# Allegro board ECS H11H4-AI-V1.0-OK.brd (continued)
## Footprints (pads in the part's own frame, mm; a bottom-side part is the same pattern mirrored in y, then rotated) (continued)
DFN6_PT065_SM2203NSQG
  rect 0.406x0.508 smd: 1(-0.65,-0.967) 2(0,-0.967) 3(0.65,-0.967) 4(0.65,0.967) 5(0,0.967) 6(-0.65,0.967)
  rect 1.016x1.016 smd: 7(-0.27,0)
  rect 0.305x0.762 smd: 8(0.59,0.03)
DFN8_NCP5359A_1
  rect 0.305x0.635 smd: 1(-0.75,-0.925) 2(-0.25,-0.925) 3(0.25,-0.925) 4(0.75,-0.925) 5(0.75,0.925) 6(0.25,0.925) 7(-0.25,0.925) 8(-0.75,0.925)
  rect 1.2x0.8 smd: 9(0,0)
DFN10_PT05_NCP1593
  rect 0.305x0.711 smd: 1(-1,-1.46) 2(-0.5,-1.46) 3(0,-1.46) 4(0.5,-1.46) 5(1,-1.46) 6(1,1.46) 7(0.5,1.46) 8(0,1.46) 9(-0.5,1.46) 10(-1,1.46)
  rect 2.5x1.8 smd: 11(0,0)
EC2_4_H5MM
  round 1.27 hole 0.813: 1(-1,0) 2(1,0)
EC2D5_6D3_H8MM
  round 1.372 hole 1.016: 1(-1.25,0) 2(1.25,0)
EC2D5_6D3_H9MM
  round 1.372 hole 1.016: 1(-1.25,0) 2(1.25,0)
EC2D5_6D3_H11MM
  round 1.372 hole 1.016: 1(-1.25,0) 2(1.25,0)
EC3D5_8_H11MM_1P
  round 1.676 hole 1.219: 1(-1.75,0)
  round 1.372 hole 1.016: 2(1.75,0)
EC3D5_8_H13MM_1P
  round 1.676 hole 1.219: 1(-1.75,0)
  round 1.372 hole 1.016: 2(1.75,0)
ETXTALS-SPAD_1
  round 1.016 hole 0.66: 1(-6.35,-1.27) 2(-6.35,1.27)
  round 1.27 hole 0.813: 3(0,-2.54) 4(0,2.54)
FB0402_2
  oval 0.572x0.508 smd: 1(-0.476,0) 2(0.476,0)
FB0603_2
  oval 0.889x0.762 smd: 1(-0.699,0) 2(0.699,0)
FB0805_2
  oval 1.143x1.397 smd: 1(-0.953,0) 2(0.953,0)
FPC_4P10_R_1
  rect 0.2x0.675 smd: 1(-1,-0.437) 2(-0.5,-0.437) 4(0.5,-0.437) 5(1,-0.437) 6(1,0.437) 7(0.5,0.437) 9(-0.5,0.437) 10(-1,0.437)
  rect 0.4x1.55 smd: 8(0,0)
FUSE_SMD_1
  rect 1.905x3.404 smd: 1(-2.223,0) 2(2.223,0)
HDMI_19P-F_SMD-HIGH-TOP_5
  rect 0.279x2.997 smd: 1(4.5,5.077) 2(4,5.077) 3(3.5,5.077) 4(3,5.077) 5(2.5,5.077) 6(2,5.077) 7(1.5,5.077) 8(1,5.077) 9(0.5,5.077) 10(0,5.077) 11(-0.5,5.077) 12(-1,5.077) 13(-1.5,5.077) 14(-2,5.077) 15(-2.5,5.077) 16(-3,5.077) 17(-3.5,5.077) 18(-4,5.077) 19(-4.5,5.077)
  oval 1.524x3.353 hole 0.914x2.743: 20(7.25,4.142) 21(-7.25,4.142)
  oval 1.524x2.235 hole 0.914x1.626: 22(7.25,-1.818) 23(-7.25,-1.818)
HOLE8_5
  round 4.064 hole 4.064 unplated: (0,0)
  round 0.66 hole 0.356: 1(0,3.992) 2(-2.823,2.823) 3(-3.992,0) 4(-2.823,-2.823) 5(0,-3.992) 6(2.823,-2.823) 7(3.992,0) 8(2.823,2.823)
J3X1
  rect 1.372x1.372 hole 1.016: 1(-2.54,0)
  round 1.372 hole 1.016: 2(0,0) 3(2.54,0)
J4X1_WAFER
  rect 1.372x1.372 hole 1.016: 1(3.81,0)
  round 1.372 hole 1.016: 2(1.27,0) 3(-1.27,0) 4(-3.81,0)
J4X2_4P
  rect 1.372x1.372 hole 1.016: 1(-3.81,-1.27)
  round 1.372 hole 1.016: 2(-3.81,1.27) 3(-1.27,-1.27) 5(1.27,-1.27) 6(1.27,1.27) 7(3.81,-1.27) 8(3.81,1.27)
J5X2_AUDIO_1
  rect 1.372x1.372 hole 1.016: 1(-5.08,-1.27)
  round 1.372 hole 1.016: 2(-5.08,1.27) 3(-2.54,-1.27) 4(-2.54,1.27) 5(0,-1.27) 6(0,1.27) 7(2.54,-1.27) 9(5.08,-1.27) 10(5.08,1.27)
J5X2_PANEL
  rect 1.372x1.372 hole 1.016: 1(-5.08,-1.27)
  round 1.372 hole 1.016: 2(-5.08,1.27) 3(-2.54,-1.27) 4(-2.54,1.27) 5(0,-1.27) 6(0,1.27) 7(2.54,-1.27) 8(2.54,1.27) 9(5.08,-1.27)
J5X2_USB_1394
  rect 1.372x1.372 hole 1.016: 1(-5.08,-1.27)
  round 1.372 hole 1.016: 2(-5.08,1.27) 3(-2.54,-1.27) 4(-2.54,1.27) 5(0,-1.27) 6(0,1.27) 7(2.54,-1.27) 8(2.54,1.27) 10(5.08,1.27)
J7X2_PANEL_10P
  rect 1.372x1.372 hole 1.016: 1(-7.62,-1.27)
  round 1.372 hole 1.016: 2(-7.62,1.27) 3(-5.08,-1.27) 4(-5.08,1.27) 5(-2.54,-1.27) 6(-2.54,1.27) 7(0,-1.27) 8(0,1.27) 9(2.54,-1.27) 11(5.08,-1.27) 12(5.08,1.27) 13(7.62,-1.27) 14(7.62,1.27)
J10X2_TPM_4P
  rect 1.372x1.372 hole 1.016: 1(-11.43,-1.27)
  round 1.372 hole 1.016: 2(-11.43,1.27) 3(-8.89,-1.27) 5(-6.35,-1.27) 6(-6.35,1.27) 7(-3.81,-1.27) 8(-3.81,1.27) 9(-1.27,-1.27) 10(-1.27,1.27) 11(1.27,-1.27) 12(1.27,1.27) 13(3.81,-1.27) 14(3.81,1.27) 15(6.35,-1.27) 16(6.35,1.27) 17(8.89,-1.27) 18(8.89,1.27) 19(11.43,-1.27) 20(11.43,1.27)
J13X2_LPT_1
  rect 1.372x1.372 hole 1.016: 1(-15.24,-1.27)
  round 1.372 hole 1.016: 2(-12.7,-1.27) 3(-10.16,-1.27) 4(-7.62,-1.27) 5(-5.08,-1.27) 6(-2.54,-1.27) 7(0,-1.27) 8(2.54,-1.27) 9(5.08,-1.27) 10(7.62,-1.27) 11(10.16,-1.27) 12(12.7,-1.27) 13(15.24,-1.27) 14(-15.24,1.27) 15(-12.7,1.27) 16(-10.16,1.27) 17(-7.62,1.27) 18(-5.08,1.27) 19(-2.54,1.27) 20(0,1.27) 21(2.54,1.27) 22(5.08,1.27) 23(7.62,1.27) 24(10.16,1.27) 25(12.7,1.27)
JOPEN_200X60_NMNP
  rect 5.08x1.524 smd: 1(0,-0.914) 2(0,0.914)
KB_MS-MINI-DIN_1
  rect 1.676x1.676 hole 1.321: 1(-1.275,1.5)
  round 1.676 hole 1.321: 2(1.275,1.5) 3(-3.4,1.5) 4(3.4,1.5) 5(-3.4,-1) 6(3.4,-1) 7(-1.275,-5.57) 8(1.275,-5.57) 9(-3.4,-5.57) 10(3.4,-5.57) 11(-3.4,-8.07) 12(3.4,-8.07)
  round 2.692 hole 2.337: G1(0,5.3) G2(-6.75,4.5) G3(6.75,4.5) G4(-6.75,-5.57) G5(6.75,-5.57)
L0805_2
  oval 1.016x1.397 smd: 1(-0.889,0) 2(0.889,0)
LGA1151-INTEL
  round 4.064 hole 4.064 unplated: (-38.12,37.5) (-38.12,-37.5) (36.89,37.5) (36.89,-37.5)
  round 3.861 hole 3.861 unplated: (-35.21,0) (25.81,18) (25.81,-18)
  round 1.016 smd: (-19.558,-19.558) (19.812,19.812)
  round 0.66 hole 0.356: 1(-38.12,41) 2(-41.62,37.5) 3(-38.12,34) 4(-34.62,37.5) 5(36.89,41) 6(33.39,37.5) 7(36.89,34) 8(40.39,37.5) 9(-38.12,-34) 10(-41.62,-37.5) 11(-38.12,-41) 12(-34.62,-37.5) 13(36.89,-34) 14(33.39,-37.5) 15(36.89,-41) 16(40.39,-37.5)
  round 0.508 smd: A4(-16.187,18.288) A5(-15.273,18.288) AT40(18.931,-14.63) AU1(-18.931,-14.63) AU39(18.016,-15.545) AU40(18.931,-15.545) AV1(-18.931,-15.545) AV2(-18.016,-15.545) AV38(17.102,-16.459) AV39(18.016,-16.459) AW2(-18.016,-16.459) AW3(-17.102,-16.459) AW37(16.187,-17.374) AW38(17.102,-17.374) AY3(-17.102,-17.374) AY4(-16.187,-17.374) B3(-17.102,17.374) B4(-16.187,17.374) B37(16.187,16.459) B38(17.102,16.459) B39(18.016,16.459) C2(-18.016,16.459) C3(-17.102,16.459) C39(18.016,15.545) C40(18.931,15.545) D1(-18.931,15.545) D2(-18.016,15.545) D40(18.931,14.63) E40(18.931,13.716)
  round 0.429 smd: A6(-14.359,18.288) A7(-13.444,18.288) A25(3.015,18.288) A26(3.929,18.288) A27(4.844,18.288) A28(5.758,18.288) A29(6.673,18.288) A30(7.587,18.288) AA5(-15.273,0) AA6(-14.359,0) AA7(-13.444,0) AA8(-12.53,0) AA33(12.53,-0.914) AA34(13.444,-0.914) AA35(14.359,-0.914) AA36(15.273,-0.914) AA37(16.187,-0.914) AA38(17.102,-0.914) AB5(-15.273,-0.914) AB6(-14.359,-0.914) AB7(-13.444,-0.914) AB8(-12.53,-0.914) AB33(12.53,-1.829) AB34(13.444,-1.829) AB35(14.359,-1.829) AB36(15.273,-1.829) AB37(16.187,-1.829) AC5(-15.273,-1.829) AC6(-14.359,-1.829) AC7(-13.444,-1.829) AC8(-12.53,-1.829) AC33(12.53,-2.743) AC34(13.444,-2.743) AC35(14.359,-2.743) AC36(15.273,-2.743) AC37(16.187,-2.743) AD3(-17.102,-2.743) AD4(-16.187,-2.743) AD5(-15.273,-2.743) AD6(-14.359,-2.743) AD7(-13.444,-2.743) AD8(-12.53,-2.743) AD33(12.53,-3.658) AD34(13.444,-3.658) AD35(14.359,-3.658) AD36(15.273,-3.658) AD37(16.187,-3.658) AE3(-17.102,-3.658) AE4(-16.187,-3.658) AE5(-15.273,-3.658) AE6(-14.359,-3.658) AE7(-13.444,-3.658) AE8(-12.53,-3.658) AE33(12.53,-4.572) AE34(13.444,-4.572) AE35(14.359,-4.572) AE36(15.273,-4.572) AE37(16.187,-4.572) AE38(17.102,-4.572) AF4(-16.187,-4.572) AF5(-15.273,-4.572) AF6(-14.359,-4.572) AF7(-13.444,-4.572) AF8(-12.53,-4.572) AF33(12.53,-5.486) AF34(13.444,-5.486) AF35(14.359,-5.486) AF36(15.273,-5.486) AF37(16.187,-5.486) AF38(17.102,-5.486) AG4(-16.187,-5.486) AG5(-15.273,-5.486) AG6(-14.359,-5.486) AG7(-13.444,-5.486) AG8(-12.53,-5.486) AG33(12.53,-6.401) AG34(13.444,-6.401) AG35(14.359,-6.401) AG36(15.273,-6.401) AG37(16.187,-6.401) AG38(17.102,-6.401) AH3(-17.102,-6.401) AH4(-16.187,-6.401) AH5(-15.273,-6.401) AH6(-14.359,-6.401) AH7(-13.444,-6.401) AH8(-12.53,-6.401) AH33(12.53,-7.315) AH34(13.444,-7.315) AH35(14.359,-7.315) AH36(15.273,-7.315) AH37(16.187,-7.315) AH38(17.102,-7.315) AJ3(-17.102,-7.315) AJ4(-16.187,-7.315) AJ5(-15.273,-7.315) AJ6(-14.359,-7.315) AJ7(-13.444,-7.315) AJ8(-12.53,-7.315) AJ9(-11.615,-7.315) AJ11(-7.587,-8.23) AJ12(-6.673,-8.23) AJ13(-5.758,-8.23) AJ14(-4.844,-8.23) AJ15(-3.929,-8.23) AJ16(-3.015,-8.23) AJ17(-2.101,-8.23) AJ18(-1.186,-8.23) AJ19(-0.272,-8.23) AJ20(0.643,-8.23) AJ21(1.557,-8.23) AJ22(2.471,-8.23) AJ23(3.386,-8.23) AJ24(4.3,-8.23) AJ25(5.215,-8.23) AJ26(6.129,-8.23) AJ27(7.043,-8.23) AJ28(7.958,-8.23) AJ29(8.872,-8.23) AJ30(9.787,-8.23) AJ31(10.701,-8.23) AJ32(11.615,-8.23) AJ33(12.53,-8.23) AJ34(13.444,-8.23) AJ35(14.359,-8.23) AJ36(15.273,-8.23) AJ37(16.187,-8.23) AJ38(17.102,-8.23) AK3(-17.102,-8.23) AK4(-16.187,-8.23) AK5(-15.273,-8.23) AK6(-14.359,-8.23) AK7(-13.444,-8.23) AK8(-12.53,-8.23) AK9(-11.615,-8.23) AK10(-10.701,-8.23) AK11(-7.587,-9.144) AK12(-6.673,-9.144) AK13(-5.758,-9.144) AK14(-4.844,-9.144) AK15(-3.929,-9.144) AK16(-3.015,-9.144) AK17(-2.101,-9.144) AK18(-1.186,-9.144) AK19(-0.272,-9.144) AK20(0.643,-9.144) AK21(1.557,-9.144) AK22(2.471,-9.144) AK23(3.386,-9.144) AK24(4.3,-9.144) AK25(5.215,-9.144) AK26(6.129,-9.144) AK27(7.043,-9.144) AK28(7.958,-9.144) AK29(8.872,-9.144) AK30(9.787,-9.144) AK31(10.701,-9.144) AK32(11.615,-9.144) AK33(12.53,-9.144) AK34(13.444,-9.144) AK35(14.359,-9.144) AK36(15.273,-9.144) AK37(16.187,-9.144) AK38(17.102,-9.144) AL3(-17.102,-9.144) AL4(-16.187,-9.144) AL5(-15.273,-9.144) AL6(-14.359,-9.144) AL7(-13.444,-9.144) AL8(-12.53,-9.144) AL9(-11.615,-9.144) AL10(-10.701,-9.144) AL11(-7.587,-10.058) AL12(-6.673,-10.058) AL13(-5.758,-10.058) AL14(-4.844,-10.058) AL15(-3.929,-10.058) AL16(-3.015,-10.058) AL17(-2.101,-10.058) AL18(-1.186,-10.058) AL19(-0.272,-10.058) AL20(0.643,-10.058) AL21(1.557,-10.058) AL22(2.471,-10.058) AL23(3.386,-10.058) AL24(4.3,-10.058) AL25(5.215,-10.058) AL26(6.129,-10.058) AL27(7.043,-10.058) AL28(7.958,-10.058) AL29(8.872,-10.058) AL30(9.787,-10.058) AL31(10.701,-10.058) AL32(11.615,-10.058) AL33(12.53,-10.058) AL34(13.444,-10.058) AL35(14.359,-10.058) AL36(15.273,-10.058) AL37(16.187,-10.058) AL38(17.102,-10.058) AM3(-17.102,-10.058) AM4(-16.187,-10.058) AM5(-15.273,-10.058) AM6(-14.359,-10.058) AM7(-13.444,-10.058) AM8(-12.53,-10.058) AM9(-11.615,-10.058) AM10(-10.701,-10.058) AM11(-7.587,-10.973) AM12(-6.673,-10.973) AM13(-5.758,-10.973) AM14(-4.844,-10.973) AM15(-3.929,-10.973) AM16(-3.015,-10.973) AM17(-2.101,-10.973) AM18(-1.186,-10.973) AM19(-0.272,-10.973) AM20(0.643,-10.973) AM21(1.557,-10.973) AM22(2.471,-10.973) AM23(3.386,-10.973) AM24(4.3,-10.973) AM25(5.215,-10.973) AM26(6.129,-10.973) AM27(7.043,-10.973) AM28(7.958,-10.973) AM29(8.872,-10.973) AM30(9.787,-10.973) AM31(10.701,-10.973) AM32(11.615,-10.973) AM33(12.53,-10.973) AM34(13.444,-10.973) AM35(14.359,-10.973) AM36(15.273,-10.973) AM37(16.187,-10.973) AM38(17.102,-10.973) AN3(-17.102,-10.973) AN4(-16.187,-10.973) AN5(-15.273,-10.973) AN6(-14.359,-10.973) AN7(-13.444,-10.973) AN8(-12.53,-10.973) AN9(-11.615,-10.973) AN10(-10.701,-10.973) AN11(-7.587,-11.887) AN12(-6.673,-11.887) AN13(-5.758,-11.887) AN14(-4.844,-11.887) AN15(-3.929,-11.887) AN16(-3.015,-11.887) AN17(-2.101,-11.887) AN18(-1.186,-11.887) AN19(-0.272,-11.887) AN20(0.643,-11.887) AN21(1.557,-11.887) AN22(2.471,-11.887) AN23(3.386,-11.887) AN24(4.3,-11.887) AN25(5.215,-11.887) AN26(6.129,-11.887) AN27(7.043,-11.887) AN28(7.958,-11.887) AN29(8.872,-11.887) AN30(9.787,-11.887) AN31(10.701,-11.887) AN32(11.615,-11.887) AN33(12.53,-11.887) AN34(13.444,-11.887) AN35(14.359,-11.887) AN36(15.273,-11.887) AN37(16.187,-11.887) AN38(17.102,-11.887) AP3(-17.102,-11.887) AP4(-16.187,-11.887) AP5(-15.273,-11.887) AP6(-14.359,-11.887) AP7(-13.444,-11.887) AP8(-12.53,-11.887) AP9(-11.615,-11.887) AP10(-10.701,-11.887) AP11(-7.587,-12.802) AP12(-6.673,-12.802) AP13(-5.758,-12.802) AP14(-4.844,-12.802) AP15(-3.929,-12.802) AP16(-3.015,-12.802) AP17(-2.101,-12.802) AP18(-1.186,-12.802) AP19(-0.272,-12.802) AP20(0.643,-12.802) AP21(1.557,-12.802) AP22(2.471,-12.802) AP23(3.386,-12.802) AP24(4.3,-12.802) AP25(5.215,-12.802) AP26(6.129,-12.802) AP27(7.043,-12.802) AP28(7.958,-12.802) AP29(8.872,-12.802) AP30(9.787,-12.802) AP31(10.701,-12.802) AP32(11.615,-12.802) AP33(12.53,-12.802) AP34(13.444,-12.802) AP35(14.359,-12.802) AP36(15.273,-12.802) AP37(16.187,-12.802) AP38(17.102,-12.802) AR3(-17.102,-12.802) AR4(-16.187,-12.802) AR5(-15.273,-12.802) AR6(-14.359,-12.802) AR7(-13.444,-12.802) AR8(-12.53,-12.802) AR9(-11.615,-12.802) AR10(-10.701,-12.802) AR11(-7.587,-13.716) AR12(-6.673,-13.716) AR13(-5.758,-13.716) AR14(-4.844,-13.716) AR15(-3.929,-13.716) AR16(-3.015,-13.716) AR17(-2.101,-13.716) AR18(-1.186,-13.716) AR19(-0.272,-13.716) AR20(0.643,-13.716) AR21(1.557,-13.716) AR22(2.471,-13.716) AR23(3.386,-13.716) AR24(4.3,-13.716) AR25(5.215,-13.716) AR26(6.129,-13.716) AR27(7.043,-13.716) AR28(7.958,-13.716) AR29(8.872,-13.716) AR30(9.787,-13.716) AR31(10.701,-13.716) AR32(11.615,-13.716) AR33(12.53,-13.716) AR34(13.444,-13.716) AR35(14.359,-13.716) AR36(15.273,-13.716) AR37(16.187,-13.716) AR38(17.102,-13.716) AT3(-17.102,-13.716) AT4(-16.187,-13.716) AT5(-15.273,-13.716) AT6(-14.359,-13.716) AT7(-13.444,-13.716) AT8(-12.53,-13.716) AT9(-11.615,-13.716) AT10(-10.701,-13.716) AT11(-7.587,-14.63) AT12(-6.673,-14.63) AT13(-5.758,-14.63) AT14(-4.844,-14.63) AT15(-3.929,-14.63) AT16(-3.015,-14.63) AT17(-2.101,-14.63) AT18(-1.186,-14.63) AT19(-0.272,-14.63) AT20(0.643,-14.63) AT21(1.557,-14.63) AT22(2.471,-14.63) AT23(3.386,-14.63) AT24(4.3,-14.63) AT25(5.215,-14.63) AT26(6.129,-14.63) AT27(7.043,-14.63) AT28(7.958,-14.63) AT29(8.872,-14.63) AT30(9.787,-14.63) AT31(10.701,-14.63) AT32(11.615,-14.63) AT33(12.53,-14.63) AT34(13.444,-14.63) AT35(14.359,-14.63) AT36(15.273,-14.63) AT37(16.187,-14.63) AT38(17.102,-14.63) AU3(-17.102,-14.63) AU4(-16.187,-14.63) AU5(-15.273,-14.63) AU6(-14.359,-14.63) AU7(-13.444,-14.63) AU8(-12.53,-14.63) AU9(-11.615,-14.63) AU10(-10.701,-14.63) AU11(-7.587,-15.545) AU12(-6.673,-15.545) AU13(-5.758,-15.545) AU14(-4.844,-15.545) AU15(-3.929,-15.545) AU16(-3.015,-15.545) AU17(-2.101,-15.545) AU18(-1.186,-15.545) AU19(-0.272,-15.545) AU20(0.643,-15.545) AU21(1.557,-15.545) AU24(4.3,-15.545) AU25(5.215,-15.545) AU26(6.129,-15.545) AU27(7.043,-15.545) AU28(7.958,-15.545) AU29(8.872,-15.545) AU30(9.787,-15.545) AU31(10.701,-15.545) AU32(11.615,-15.545) AU33(12.53,-15.545) AU34(13.444,-15.545) AU35(14.359,-15.545) AU36(15.273,-15.545) AU37(16.187,-15.545) AU38(17.102,-15.545) AV3(-17.102,-15.545) AV4(-16.187,-15.545) AV5(-15.273,-15.545) AV6(-14.359,-15.545) AV7(-13.444,-15.545) AV8(-12.53,-15.545) AV9(-11.615,-15.545) AV10(-10.701,-15.545) AV11(-7.587,-16.459) AV12(-6.673,-16.459) AV13(-5.758,-16.459) AV14(-4.844,-16.459) AV24(4.3,-16.459) AV25(5.215,-16.459) AV28(7.958,-16.459) AV29(8.872,-16.459) AV37(16.187,-16.459) AW4(-16.187,-16.459) AW9(-11.615,-16.459) AW10(-10.701,-16.459) AW11(-7.587,-17.374) AW12(-6.673,-17.374) AW13(-5.758,-17.374) AW14(-4.844,-17.374) AY10(-10.701,-17.374) B5(-15.273,17.374) B6(-14.359,17.374) B7(-13.444,17.374) B25(3.015,17.374) B26(3.929,17.374) B27(4.844,17.374) B28(5.758,17.374) B29(6.673,17.374) B30(7.587,17.374) B31(10.701,16.459) B32(11.615,16.459) B33(12.53,16.459) B34(13.444,16.459) B35(14.359,16.459) B36(15.273,16.459) C4(-16.187,16.459) C5(-15.273,16.459) C6(-14.359,16.459) C7(-13.444,16.459) C8(-12.53,16.459) C9(-11.615,16.459) C12(-8.872,16.459) C13(-7.958,16.459) C14(-7.043,16.459) C15(-6.129,16.459) C16(-5.215,16.459) C17(-4.3,16.459) C25(3.015,16.459) C26(3.929,16.459) C27(4.844,16.459) C28(5.758,16.459) C29(6.673,16.459) C30(7.587,16.459) C31(10.701,15.545) C32(11.615,15.545) C33(12.53,15.545) C34(13.444,15.545) C35(14.359,15.545) C36(15.273,15.545) C37(16.187,15.545) C38(17.102,15.545) D3(-17.102,15.545) D4(-16.187,15.545) D5(-15.273,15.545) D6(-14.359,15.545) D7(-13.444,15.545) D8(-12.53,15.545) D9(-11.615,15.545) D10(-10.701,15.545) D11(-9.787,15.545) D12(-8.872,15.545) D13(-7.958,15.545) D14(-7.043,15.545) D15(-6.129,15.545) D16(-5.215,15.545) D17(-4.3,15.545) D24(2.101,15.545) D25(3.015,15.545) D26(3.929,15.545) D27(4.844,15.545) D28(5.758,15.545) D29(6.673,15.545) D30(7.587,15.545) D31(10.701,14.63) D32(11.615,14.63) D33(12.53,14.63) D34(13.444,14.63) D35(14.359,14.63) D36(15.273,14.63) D37(16.187,14.63) D38(17.102,14.63) D39(18.016,14.63) E3(-17.102,14.63) E4(-16.187,14.63) E5(-15.273,14.63) E6(-14.359,14.63) E7(-13.444,14.63) E8(-12.53,14.63) E9(-11.615,14.63) E10(-10.701,14.63) E11(-9.787,14.63) E12(-8.872,14.63) E13(-7.958,14.63) E14(-7.043,14.63) E15(-6.129,14.63) E16(-5.215,14.63) E17(-4.3,14.63) E18(-3.386,14.63) E19(-2.471,14.63) E21(-0.643,14.63) E23(1.186,14.63) E24(2.101,14.63) E25(3.015,14.63) E26(3.929,14.63) E27(4.844,14.63) E28(5.758,14.63) E29(6.673,14.63) E30(7.587,14.63) E31(10.701,13.716) E32(11.615,13.716) E33(12.53,13.716) E34(13.444,13.716) E35(14.359,13.716) E36(15.273,13.716) E37(16.187,13.716) E38(17.102,13.716) E39(18.016,13.716) F4(-16.187,13.716) F5(-15.273,13.716) F6(-14.359,13.716) F7(-13.444,13.716) F8(-12.53,13.716) F9(-11.615,13.716) F10(-10.701,13.716) F11(-9.787,13.716) F12(-8.872,13.716) F13(-7.958,13.716) F14(-7.043,13.716) F15(-6.129,13.716) F16(-5.215,13.716) F17(-4.3,13.716) F18(-3.386,13.716) F19(-2.471,13.716) F20(-1.557,13.716) F21(-0.643,13.716) F22(0.272,13.716) F23(1.186,13.716) F24(2.101,13.716) F25(3.015,13.716) F26(3.929,13.716) F27(4.844,13.716) F28(5.758,13.716) F29(6.673,13.716) F30(7.587,13.716) F31(10.701,12.802) F32(11.615,12.802) F33(12.53,12.802) F34(13.444,12.802) F35(14.359,12.802) F36(15.273,12.802) F37(16.187,12.802) F38(17.102,12.802) F39(18.016,12.802) F40(18.931,12.802) G3(-17.102,12.802) G4(-16.187,12.802) G5(-15.273,12.802) G6(-14.359,12.802) G7(-13.444,12.802) G8(-12.53,12.802) G9(-11.615,12.802) G10(-10.701,12.802) G11(-9.787,12.802) G12(-8.872,12.802) G13(-7.958,12.802) G14(-7.043,12.802) G15(-6.129,12.802) G16(-5.215,12.802) G17(-4.3,12.802) G18(-3.386,12.802) G19(-2.471,12.802) G20(-1.557,12.802) G21(-0.643,12.802) G22(0.272,12.802) G23(1.186,12.802) G24(2.101,12.802) G25(3.015,12.802) G26(3.929,12.802) G27(4.844,12.802) G28(5.758,12.802) G29(6.673,12.802) G30(7.587,12.802) G31(10.701,11.887) G32(11.615,11.887) G33(12.53,11.887) G34(13.444,11.887) G35(14.359,11.887) G36(15.273,11.887) G37(16.187,11.887) G38(17.102,11.887) G39(18.016,11.887) G40(18.931,11.887) H4(-16.187,11.887) H5(-15.273,11.887) H6(-14.359,11.887) H7(-13.444,11.887) H8(-12.53,11.887) H9(-11.615,11.887) H10(-10.701,11.887) H11(-9.787,11.887) H12(-8.872,11.887) H13(-7.958,11.887) H14(-7.043,11.887) H15(-6.129,11.887) H16(-5.215,11.887) H17(-4.3,11.887) H18(-3.386,11.887) H19(-2.471,11.887) H20(-1.557,11.887) H21(-0.643,11.887) H22(0.272,11.887) H23(1.186,11.887) H24(2.101,11.887) H25(3.015,11.887) H26(3.929,11.887) H27(4.844,11.887) H28(5.758,11.887) H29(6.673,11.887) H30(7.587,11.887) H31(10.701,10.973) H32(11.615,10.973) H33(12.53,10.973) H34(13.444,10.973) H35(14.359,10.973) H36(15.273,10.973) H37(16.187,10.973) H38(17.102,10.973) H39(18.016,10.973) H40(18.931,10.973) J3(-17.102,10.973) J4(-16.187,10.973) J5(-15.273,10.973) J6(-14.359,10.973) J7(-13.444,10.973) J8(-12.53,10.973) J9(-11.615,10.973) J10(-10.701,10.973) J11(-9.787,10.973) J12(-8.872,10.973) J13(-7.958,10.973) J14(-7.043,10.973) J15(-6.129,10.973) J16(-5.215,10.973) J17(-4.3,10.973) J18(-3.386,10.973) J19(-2.471,10.973) J20(-1.557,10.973) J21(-0.643,10.973) J22(0.272,10.973) J23(1.186,10.973) J24(2.101,10.973) J25(3.015,10.973) J26(3.929,10.973) J27(4.844,10.973) J28(5.758,10.973) J29(6.673,10.973) J30(7.587,10.973) J31(10.701,10.058) J32(11.615,10.058) J33(12.53,10.058) J34(13.444,10.058) J35(14.359,10.058) J36(15.273,10.058) J37(16.187,10.058) J38(17.102,10.058) J39(18.016,10.058) J40(18.931,10.058) K4(-16.187,10.058) K5(-15.273,10.058) K6(-14.359,10.058) K7(-13.444,10.058) K8(-12.53,10.058) K9(-11.615,10.058) K10(-10.701,10.058) K11(-9.787,10.058) K12(-8.872,10.058) K13(-7.958,10.058) K14(-7.043,10.058) K15(-6.129,10.058) K16(-5.215,10.058) K17(-4.3,10.058) K18(-3.386,10.058) K19(-2.471,10.058) K20(-1.557,10.058) K21(-0.643,10.058) K22(0.272,10.058) K23(1.186,10.058) K24(2.101,10.058) K25(3.015,10.058) K26(3.929,10.058) K27(4.844,10.058) K28(5.758,10.058) K29(6.673,10.058) K30(7.587,10.058) K31(10.701,9.144) K32(11.615,9.144) K33(12.53,9.144) K34(13.444,9.144) K35(14.359,9.144) K36(15.273,9.144) K37(16.187,9.144) K38(17.102,9.144) K39(18.016,9.144) K40(18.931,9.144) L3(-17.102,9.144) L4(-16.187,9.144) L5(-15.273,9.144) L6(-14.359,9.144) L7(-13.444,9.144) L8(-12.53,9.144) L9(-11.615,9.144) L10(-10.701,9.144) L11(-9.787,9.144) L12(-8.872,9.144) L13(-7.958,9.144) L14(-7.043,9.144) L15(-6.129,9.144) L16(-5.215,9.144) L17(-4.3,9.144) L18(-3.386,9.144) L19(-2.471,9.144) L20(-1.557,9.144) L21(-0.643,9.144) L22(0.272,9.144) L23(1.186,9.144) L24(2.101,9.144) L25(3.015,9.144) L26(3.929,9.144) L27(4.844,9.144) L28(5.758,9.144) L29(6.673,9.144) L30(7.587,9.144) L31(10.701,8.23) L32(11.615,8.23) L33(12.53,8.23) L34(13.444,8.23) L35(14.359,8.23) L36(15.273,8.23) L37(16.187,8.23) L38(17.102,8.23) L39(18.016,8.23) L40(18.931,8.23) M4(-16.187,8.23) M5(-15.273,8.23) M6(-14.359,8.23) M7(-13.444,8.23) M8(-12.53,8.23) M9(-11.615,8.23) M10(-10.701,8.23) M11(-9.787,8.23) M12(-8.872,8.23) M13(-7.958,8.23) M14(-7.043,8.23) M15(-6.129,8.23) M16(-5.215,8.23) M17(-4.3,8.23) M18(-3.386,8.23) M19(-2.471,8.23) M20(-1.557,8.23) M21(-0.643,8.23) M22(0.272,8.23) M23(1.186,8.23) M24(2.101,8.23) M25(3.015,8.23) M26(3.929,8.23) M27(4.844,8.23) M28(5.758,8.23) M29(6.673,8.23) M30(7.587,8.23) M32(11.615,7.315) M33(12.53,7.315) M34(13.444,7.315) M35(14.359,7.315) M36(15.273,7.315) M37(16.187,7.315) M38(17.102,7.315) M39(18.016,7.315) M40(18.931,7.315) N3(-17.102,7.315) N4(-16.187,7.315) N5(-15.273,7.315) N6(-14.359,7.315) N7(-13.444,7.315) N8(-12.53,7.315) N33(12.53,6.401) N34(13.444,6.401) N35(14.359,6.401) N36(15.273,6.401) N37(16.187,6.401) N38(17.102,6.401) N39(18.016,6.401) N40(18.931,6.401) P4(-16.187,6.401) P5(-15.273,6.401) P6(-14.359,6.401) P7(-13.444,6.401) P8(-12.53,6.401) P33(12.53,5.486) P34(13.444,5.486) P35(14.359,5.486) P36(15.273,5.486) P37(16.187,5.486) P38(17.102,5.486) P39(18.016,5.486) P40(18.931,5.486) R3(-17.102,5.486) R4(-16.187,5.486) R5(-15.273,5.486) R6(-14.359,5.486) R7(-13.444,5.486) R8(-12.53,5.486) R33(12.53,4.572) R34(13.444,4.572) R35(14.359,4.572) R36(15.273,4.572) R37(16.187,4.572) R38(17.102,4.572) R39(18.016,4.572) R40(18.931,4.572) T4(-16.187,4.572) T5(-15.273,4.572) T6(-14.359,4.572) T7(-13.444,4.572) T8(-12.53,4.572) T33(12.53,3.658) T34(13.444,3.658) T35(14.359,3.658) T36(15.273,3.658) T37(16.187,3.658) T38(17.102,3.658) T39(18.016,3.658) T40(18.931,3.658) U4(-16.187,3.658) U5(-15.273,3.658) U6(-14.359,3.658) U7(-13.444,3.658) U8(-12.53,3.658) U33(12.53,2.743) U34(13.444,2.743) U35(14.359,2.743) U36(15.273,2.743) U37(16.187,2.743) U38(17.102,2.743) U39(18.016,2.743) U40(18.931,2.743) V4(-16.187,2.743) V5(-15.273,2.743) V6(-14.359,2.743) V7(-13.444,2.743) V8(-12.53,2.743) V33(12.53,1.829) V34(13.444,1.829) V35(14.359,1.829) V36(15.273,1.829) V37(16.187,1.829) V38(17.102,1.829) V39(18.016,1.829) V40(18.931,1.829) W4(-16.187,1.829) W5(-15.273,1.829) W6(-14.359,1.829) W7(-13.444,1.829) W8(-12.53,1.829) W33(12.53,0.914) W34(13.444,0.914) W35(14.359,0.914) W36(15.273,0.914) W37(16.187,0.914) W38(17.102,0.914) Y5(-15.273,0.914) Y6(-14.359,0.914) Y7(-13.444,0.914) Y8(-12.53,0.914) Y33(12.53,0) Y34(13.444,0) Y35(14.359,0) Y36(15.273,0) Y37(16.187,0) Y38(17.102,0)
  oval 0.356x0.457 smd: A11(-9.787,18.288) A12(-8.872,18.288) A13(-7.958,18.288) A14(-7.043,18.288) A15(-6.129,18.288) A16(-5.215,18.288) A17(-4.3,18.288) A18(-3.386,18.288) A23(1.186,18.288) A24(2.101,18.288) AU22(2.471,-15.545) AU23(3.386,-15.545) AV15(-3.929,-16.459) AV16(-3.015,-16.459) AV17(-2.101,-16.459) AV18(-1.186,-16.459) AV19(-0.272,-16.459) AV20(0.643,-16.459) AV21(1.557,-16.459) AV22(2.471,-16.459) AV23(3.386,-16.459) AV26(6.129,-16.459) AV27(7.043,-16.459) AV30(9.787,-16.459) AV31(10.701,-16.459) AV32(11.615,-16.459) AV33(12.53,-16.459) AV34(13.444,-16.459) AV35(14.359,-16.459) AV36(15.273,-16.459) AW5(-15.273,-16.459) AW6(-14.359,-16.459) AW7(-13.444,-16.459) AW8(-12.53,-16.459) AW15(-3.929,-17.374) AW16(-3.015,-17.374) AW17(-2.101,-17.374) AW18(-1.186,-17.374) AW23(3.386,-17.374) AW24(4.3,-17.374) AW25(5.215,-17.374) AW26(6.129,-17.374) AW27(7.043,-17.374) AW28(7.958,-17.374) AW29(8.872,-17.374) AW30(9.787,-17.374) AW31(10.701,-17.374) AW32(11.615,-17.374) AW33(12.53,-17.374) AW34(13.444,-17.374) AW35(14.359,-17.374) AW36(15.273,-17.374) AY5(-15.273,-17.374) AY6(-14.359,-17.374) AY7(-13.444,-17.374) AY8(-12.53,-17.374) AY9(-11.615,-17.374) AY11(-7.587,-18.288) AY12(-6.673,-18.288) AY13(-5.758,-18.288) AY14(-4.844,-18.288) AY15(-3.929,-18.288) AY16(-3.015,-18.288) AY17(-2.101,-18.288) AY18(-1.186,-18.288) AY23(3.386,-18.288) AY24(4.3,-18.288) AY25(5.215,-18.288) AY26(6.129,-18.288) AY27(7.043,-18.288) AY28(7.958,-18.288) AY29(8.872,-18.288) AY30(9.787,-18.288) AY31(10.701,-18.288) B8(-12.53,17.374) B9(-11.615,17.374) B10(-10.701,17.374) B11(-9.787,17.374) B12(-8.872,17.374) B13(-7.958,17.374) B14(-7.043,17.374) B15(-6.129,17.374) B16(-5.215,17.374) B17(-4.3,17.374) B18(-3.386,17.374) B23(1.186,17.374) B24(2.101,17.374) C10(-10.701,16.459) C11(-9.787,16.459) C18(-3.386,16.459) C19(-2.471,16.459) C20(-1.557,16.459) C21(-0.643,16.459) C22(0.272,16.459) C23(1.186,16.459) C24(2.101,16.459) D18(-3.386,15.545) D19(-2.471,15.545) D20(-1.557,15.545) D21(-0.643,15.545) D22(0.272,15.545) D23(1.186,15.545) E20(-1.557,14.63) E22(0.272,14.63)
  oval 0.457x0.356 smd: AA3(-17.102,0) AA4(-16.187,0) AB3(-17.102,-0.914) AB4(-16.187,-0.914) AB38(17.102,-1.829) AB39(18.016,-1.829) AB40(18.931,-1.829) AC1(-18.931,-1.829) AC2(-18.016,-1.829) AC3(-17.102,-1.829) AC4(-16.187,-1.829) AC38(17.102,-2.743) AC39(18.016,-2.743) AC40(18.931,-2.743) AD1(-18.931,-2.743) AD2(-18.016,-2.743) AD38(17.102,-3.658) AD39(18.016,-3.658) AD40(18.931,-3.658) AE1(-18.931,-3.658) AE2(-18.016,-3.658) AE39(18.016,-4.572) AE40(18.931,-4.572) AF1(-18.931,-4.572) AF2(-18.016,-4.572) AF3(-17.102,-4.572) AF39(18.016,-5.486) AF40(18.931,-5.486) AG1(-18.931,-5.486) AG2(-18.016,-5.486) AG3(-17.102,-5.486) AG39(18.016,-6.401) AG40(18.931,-6.401) AH1(-18.931,-6.401) AH2(-18.016,-6.401) AH39(18.016,-7.315) AH40(18.931,-7.315) AJ1(-18.931,-7.315) AJ2(-18.016,-7.315) AJ39(18.016,-8.23) AJ40(18.931,-8.23) AK1(-18.931,-8.23) AK2(-18.016,-8.23) AK39(18.016,-9.144) AK40(18.931,-9.144) AL1(-18.931,-9.144) AL2(-18.016,-9.144) AL39(18.016,-10.058) AL40(18.931,-10.058) AM1(-18.931,-10.058) AM2(-18.016,-10.058) AM39(18.016,-10.973) AM40(18.931,-10.973) AN1(-18.931,-10.973) AN2(-18.016,-10.973) AN39(18.016,-11.887) AN40(18.931,-11.887) AP1(-18.931,-11.887) AP2(-18.016,-11.887) AP39(18.016,-12.802) AP40(18.931,-12.802) AR1(-18.931,-12.802) AR2(-18.016,-12.802) AR39(18.016,-13.716) AR40(18.931,-13.716) AT1(-18.931,-13.716) AT2(-18.016,-13.716) AT39(18.016,-14.63) AU2(-18.016,-14.63) E1(-18.931,14.63) E2(-18.016,14.63) F1(-18.931,13.716) F2(-18.016,13.716) F3(-17.102,13.716) G1(-18.931,12.802) G2(-18.016,12.802) H1(-18.931,11.887) H2(-18.016,11.887) H3(-17.102,11.887) J1(-18.931,10.973) J2(-18.016,10.973) K1(-18.931,10.058) K2(-18.016,10.058) K3(-17.102,10.058) L1(-18.931,9.144) L2(-18.016,9.144) M1(-18.931,8.23) M2(-18.016,8.23) M3(-17.102,8.23) N1(-18.931,7.315) N2(-18.016,7.315) P1(-18.931,6.401) P2(-18.016,6.401) P3(-17.102,6.401) R1(-18.931,5.486) R2(-18.016,5.486) T1(-18.931,4.572) T2(-18.016,4.572) T3(-17.102,4.572) U1(-18.931,3.658) U2(-18.016,3.658) U3(-17.102,3.658) V1(-18.931,2.743) V2(-18.016,2.743) V3(-17.102,2.743) W1(-18.931,1.829) W2(-18.016,1.829) W3(-17.102,1.829) Y3(-17.102,0.914) Y4(-16.187,0.914)
LQFP48
  round 1.016 smd: (-4.254,-4.239) (4.263,4.278)
  rect 1.524x0.432 smd: 1(-4.25,2.826) 12(-4.25,-2.826) 25(4.25,-2.826) 36(4.25,2.826)
  rect 1.524x0.279 smd: 2(-4.25,2.25) 3(-4.25,1.75) 4(-4.25,1.25) 5(-4.25,0.75) 6(-4.25,0.25) 7(-4.25,-0.25) 8(-4.25,-0.75) 9(-4.25,-1.25) 10(-4.25,-1.75) 11(-4.25,-2.25) 26(4.25,-2.25) 27(4.25,-1.75) 28(4.25,-1.25) 29(4.25,-0.75) 30(4.25,-0.25) 31(4.25,0.25) 32(4.25,0.75) 33(4.25,1.25) 34(4.25,1.75) 35(4.25,2.25)
  rect 0.432x1.524 smd: 13(-2.826,-4.25) 24(2.826,-4.25) 37(2.826,4.25) 48(-2.826,4.25)
  rect 0.279x1.524 smd: 14(-2.25,-4.25) 15(-1.75,-4.25) 16(-1.25,-4.25) 17(-0.75,-4.25) 18(-0.25,-4.25) 19(0.25,-4.25) 20(0.75,-4.25) 21(1.25,-4.25) 22(1.75,-4.25) 23(2.25,-4.25) 38(2.25,4.25) 39(1.75,4.25) 40(1.25,4.25) 41(0.75,4.25) 42(0.25,4.25) 43(-0.25,4.25) 44(-0.75,4.25) 45(-1.25,4.25) 46(-1.75,4.25) 47(-2.25,4.25)
LQFP128_PT04
  round 1.016 smd: (-7.62,-7.62) (7.62,7.62)
  rect 1.626x0.305 smd: 1(-7.7,6.251) 32(-7.7,-6.251) 65(7.7,-6.251) 96(7.7,6.251)
  rect 1.626x0.203 smd: 2(-7.7,5.8) 3(-7.7,5.4) 4(-7.7,5) 5(-7.7,4.6) 6(-7.7,4.2) 7(-7.7,3.8) 8(-7.7,3.4) 9(-7.7,3) 10(-7.7,2.6) 11(-7.7,2.2) 12(-7.7,1.8) 13(-7.7,1.4) 14(-7.7,1) 15(-7.7,0.6) 16(-7.7,0.2) 17(-7.7,-0.2) 18(-7.7,-0.6) 19(-7.7,-1) 20(-7.7,-1.4) 21(-7.7,-1.8) 22(-7.7,-2.2) 23(-7.7,-2.6) 24(-7.7,-3) 25(-7.7,-3.4) 26(-7.7,-3.8) 27(-7.7,-4.2) 28(-7.7,-4.6) 29(-7.7,-5) 30(-7.7,-5.4) 31(-7.7,-5.8) 66(7.7,-5.8) 67(7.7,-5.4) 68(7.7,-5) 69(7.7,-4.6) 70(7.7,-4.2) 71(7.7,-3.8) 72(7.7,-3.4) 73(7.7,-3) 74(7.7,-2.6) 75(7.7,-2.2) 76(7.7,-1.8) 77(7.7,-1.4) 78(7.7,-1) 79(7.7,-0.6) 80(7.7,-0.2) 81(7.7,0.2) 82(7.7,0.6) 83(7.7,1) 84(7.7,1.4) 85(7.7,1.8) 86(7.7,2.2) 87(7.7,2.6) 88(7.7,3) 89(7.7,3.4) 90(7.7,3.8) 91(7.7,4.2) 92(7.7,4.6) 93(7.7,5) 94(7.7,5.4) 95(7.7,5.8)
  rect 0.305x1.626 smd: 33(-6.251,-7.7) 64(6.251,-7.7) 97(6.251,7.7) 128(-6.251,7.7)
  rect 0.203x1.626 smd: 34(-5.8,-7.7) 35(-5.4,-7.7) 36(-5,-7.7) 37(-4.6,-7.7) 38(-4.2,-7.7) 39(-3.8,-7.7) 40(-3.4,-7.7) 41(-3,-7.7) 42(-2.6,-7.7) 43(-2.2,-7.7) 44(-1.8,-7.7) 45(-1.4,-7.7) 46(-1,-7.7) 47(-0.6,-7.7) 48(-0.2,-7.7) 49(0.2,-7.7) 50(0.6,-7.7) 51(1,-7.7) 52(1.4,-7.7) 53(1.8,-7.7) 54(2.2,-7.7) 55(2.6,-7.7) 56(3,-7.7) 57(3.4,-7.7) 58(3.8,-7.7) 59(4.2,-7.7) 60(4.6,-7.7) 61(5,-7.7) 62(5.4,-7.7) 63(5.8,-7.7) 98(5.8,7.7) 99(5.4,7.7) 100(5,7.7) 101(4.6,7.7) 102(4.2,7.7) 103(3.8,7.7) 104(3.4,7.7) 105(3,7.7) 106(2.6,7.7) 107(2.2,7.7) 108(1.8,7.7) 109(1.4,7.7) 110(1,7.7) 111(0.6,7.7) 112(0.2,7.7) 113(-0.2,7.7) 114(-0.6,7.7) 115(-1,7.7) 116(-1.4,7.7) 117(-1.8,7.7) 118(-2.2,7.7) 119(-2.6,7.7) 120(-3,7.7) 121(-3.4,7.7) 122(-3.8,7.7) 123(-4.2,7.7) 124(-4.6,7.7) 125(-5,7.7) 126(-5.4,7.7) 127(-5.8,7.7)
PCIE_X16_164P_4
  round 2.362 hole 2.362 unplated: (0,0) (0,-73.15)
  rect 1.067x1.067 hole 0.711: A1(1.25,11.65)
  round 1.067 hole 0.711: A2(3.25,10.65) A3(1.25,9.65) A4(3.25,8.65) A5(1.25,7.65) A6(3.25,6.65) A7(1.25,5.65) A8(3.25,4.65) A9(1.25,3.65) A10(3.25,2.65) A11(1.25,1.65) A12(3.25,-1.35) A13(1.25,-2.35) A14(3.25,-3.35) A15(1.25,-4.35) A16(3.25,-5.35) A17(1.25,-6.35) A18(3.25,-7.35) A19(1.25,-8.35) A20(3.25,-9.35) A21(1.25,-10.35) A22(3.25,-11.35) A23(1.25,-12.35) A24(3.25,-13.35) A25(1.25,-14.35) A26(3.25,-15.35) A27(1.25,-16.35) A28(3.25,-17.35) A29(1.25,-18.35) A30(3.25,-19.35) A31(1.25,-20.35) A32(3.25,-21.35) A33(1.25,-22.35) A34(3.25,-23.35) A35(1.25,-24.35) A36(3.25,-25.35) A37(1.25,-26.35) A38(3.25,-27.35) A39(1.25,-28.35) A40(3.25,-29.35) A41(1.25,-30.35) A42(3.25,-31.35) A43(1.25,-32.35) A44(3.25,-33.35) A45(1.25,-34.35) A46(3.25,-35.35) A47(1.25,-36.35) A48(3.25,-37.35) A49(1.25,-38.35) A50(3.25,-39.35) A51(1.25,-40.35) A52(3.25,-41.35) A53(1.25,-42.35) A54(3.25,-43.35) A55(1.25,-44.35) A56(3.25,-45.35) A57(1.25,-46.35) A58(3.25,-47.35) A59(1.25,-48.35) A60(3.25,-49.35) A61(1.25,-50.35) A62(3.25,-51.35) A63(1.25,-52.35) A64(3.25,-53.35) A65(1.25,-54.35) A66(3.25,-55.35) A67(1.25,-56.35) A68(3.25,-57.35) A69(1.25,-58.35) A70(3.25,-59.35) A71(1.25,-60.35) A72(3.25,-61.35) A73(1.25,-62.35) A74(3.25,-63.35) A75(1.25,-64.35) A76(3.25,-65.35) A77(1.25,-66.35) A78(3.25,-67.35) A79(1.25,-68.35) A80(3.25,-69.35) A81(1.25,-70.35) A82(3.25,-71.35) B1(-1.25,11.65) B2(-3.25,10.65) B3(-1.25,9.65) B4(-3.25,8.65) B5(-1.25,7.65) B6(-3.25,6.65) B7(-1.25,5.65) B8(-3.25,4.65) B9(-1.25,3.65) B10(-3.25,2.65) B11(-1.25,1.65) B12(-3.25,-1.35) B13(-1.25,-2.35) B14(-3.25,-3.35) B15(-1.25,-4.35) B16(-3.25,-5.35) B17(-1.25,-6.35) B18(-3.25,-7.35) B19(-1.25,-8.35) B20(-3.25,-9.35) B21(-1.25,-10.35) B22(-3.25,-11.35) B23(-1.25,-12.35) B24(-3.25,-13.35) B25(-1.25,-14.35) B26(-3.25,-15.35) B27(-1.25,-16.35) B28(-3.25,-17.35) B29(-1.25,-18.35) B30(-3.25,-19.35) B31(-1.25,-20.35) B32(-3.25,-21.35) B33(-1.25,-22.35) B34(-3.25,-23.35) B35(-1.25,-24.35) B36(-3.25,-25.35) B37(-1.25,-26.35) B38(-3.25,-27.35) B39(-1.25,-28.35) B40(-3.25,-29.35) B41(-1.25,-30.35) B42(-3.25,-31.35) B43(-1.25,-32.35) B44(-3.25,-33.35) B45(-1.25,-34.35) B46(-3.25,-35.35) B47(-1.25,-36.35) B48(-3.25,-37.35) B49(-1.25,-38.35) B50(-3.25,-39.35) B51(-1.25,-40.35) B52(-3.25,-41.35) B53(-1.25,-42.35) B54(-3.25,-43.35) B55(-1.25,-44.35) B56(-3.25,-45.35) B57(-1.25,-46.35) B58(-3.25,-47.35) B59(-1.25,-48.35) B60(-3.25,-49.35) B61(-1.25,-50.35) B62(-3.25,-51.35) B63(-1.25,-52.35) B64(-3.25,-53.35) B65(-1.25,-54.35) B66(-3.25,-55.35) B67(-1.25,-56.35) B68(-3.25,-57.35) B69(-1.25,-58.35) B70(-3.25,-59.35) B71(-1.25,-60.35) B72(-3.25,-61.35) B73(-1.25,-62.35) B74(-3.25,-63.35) B75(-1.25,-64.35) B76(-3.25,-65.35) B77(-1.25,-66.35) B78(-3.25,-67.35) B79(-1.25,-68.35) B80(-3.25,-69.35) B81(-1.25,-70.35) B82(-3.25,-71.35)
PSOP8_W150_PT50_PAD-UP7719B_1
  rect 0.711x1.524 smd: 1(-1.905,-2.75) 2(-0.635,-2.75) 3(0.635,-2.75) 4(1.905,-2.75) 5(1.905,2.75) 6(0.635,2.75) 7(-0.635,2.75) 8(-1.905,2.75)
  rect 3.2x2.3 smd: 9(0,0)
Q_TDSON8-GDS-4
  rect 0.762x1.27 smd: D1(-1.905,2.857) D2(-0.635,2.857) D3(0.635,2.857) D4(1.905,2.857) G(1.905,-2.857) S1(-1.905,-2.857) S2(-0.635,-2.857) S3(0.635,-2.857)
  custom 0.902x0.902 smd: D5(0,1.054)
QFN24_PT04_G5383A_1
  oval 0.711x0.203 smd: 1(-1.5,1.2) 2(-1.5,0.8) 3(-1.5,0.4) 4(-1.5,0) 5(-1.5,-0.4) 6(-1.5,-0.8) 7(-1.5,-1.2) 13(1.5,-1.2) 14(1.5,-0.8) 15(1.5,-0.4) 16(1.5,0) 17(1.5,0.4) 18(1.5,0.8) 19(1.5,1.2)
  oval 0.203x0.711 smd: 8(-0.8,-1.5) 9(-0.4,-1.5) 10(0,-1.5) 11(0.4,-1.5) 12(0.8,-1.5) 20(0.8,1.5) 21(0.4,1.5) 22(0,1.5) 23(-0.4,1.5) 24(-0.8,1.5)
  custom 0.2x0.2 smd: 25(0,0.5)
  custom 0.275x0.275 smd: 26(0,-0.35)
QFN32_PT04_NCP81102
  oval 0.66x0.203 smd: 1(-1.925,1.4) 2(-1.925,1) 3(-1.925,0.6) 4(-1.925,0.2) 5(-1.925,-0.2) 6(-1.925,-0.6) 7(-1.925,-1) 8(-1.925,-1.4) 17(1.925,-1.4) 18(1.925,-1) 19(1.925,-0.6) 20(1.925,-0.2) 21(1.925,0.2) 22(1.925,0.6) 23(1.925,1) 24(1.925,1.4)
  oval 0.203x0.66 smd: 9(-1.4,-1.925) 10(-1,-1.925) 11(-0.6,-1.925) 12(-0.2,-1.925) 13(0.2,-1.925) 14(0.6,-1.925) 15(1,-1.925) 16(1.4,-1.925) 25(1.4,1.925) 26(1,1.925) 27(0.6,1.925) 28(0.2,1.925) 29(-0.2,1.925) 30(-0.6,1.925) 31(-1,1.925) 32(-1.4,1.925)
  rect 2.7x2.7 smd: 33(0,0)
QFN32_PT04_UP1740Q_2
  round 0 smd: (-0.6,-2.1) (-0.2,-2.1) (0.046,-0.7) (0.2,-2.1) (0.6,-2.1) (1,-2.1) (1.4,-2.1) (2.1,1.4) (2.1,1) (2.1,0.6) (2.1,0.2) (2.1,-0.2) (2.1,-0.6) (2.1,-1) (2.1,-1.4)
  rect 0.8x0.2 smd: 1(-2.1,1.4) 2(-2.1,1) 3(-2.1,0.6) 4(-2.1,0.2) 5(-2.1,-0.2) 6(-2.1,-0.6) 7(-2.1,-1) 8(-2.1,-1.4)
  rect 0.2x0.8 smd: 9(-1.4,-2.1) 10(-1,-2.1) 14(1.4,2.1) 15(1,2.1) 16(0.6,2.1) 17(0.2,2.1) 18(-0.2,2.1) 19(-0.6,2.1) 20(-1,2.1) 21(-1.4,2.1)
  custom 0.2x0.2 smd: 11(0.4,-2.1) 13(2.1,0.8)
  custom 0.4x0.4 smd: 12(0.046,-0.7)
  rect 1.13x1.1 smd: 22(-0.88,0.9)
  rect 1.41x1.06 smd: 23(0.74,0.92)
QFN32_PT04_UP1740Q_3
  round 0 smd: (-0.6,-2.1) (-0.2,-2.1) (0.046,-0.7) (0.2,-2.1) (0.6,-2.1) (1,-2.1) (1.4,-2.1) (2.1,1.4) (2.1,1) (2.1,0.6) (2.1,0.2) (2.1,-0.2) (2.1,-0.6) (2.1,-1) (2.1,-1.4)
  rect 0.8x0.2 smd: 1(-2.1,1.4) 2(-2.1,1) 3(-2.1,0.6) 4(-2.1,0.2) 5(-2.1,-0.2) 6(-2.1,-0.6) 7(-2.1,-1) 8(-2.1,-1.4)
  rect 0.2x0.8 smd: 9(-1.4,-2.1) 10(-1,-2.1) 14(1.4,2.1) 15(1,2.1) 16(0.6,2.1) 17(0.2,2.1) 18(-0.2,2.1) 19(-0.6,2.1) 20(-1,2.1) 21(-1.4,2.1)
  custom 0.2x0.2 smd: 11(0.4,-2.1) 13(2.1,0.8)
  custom 0.4x0.4 smd: 12(0.046,-0.7)
  rect 1.13x1.1 smd: 22(-0.88,0.9)
  rect 1.41x1.06 smd: 23(0.74,0.92)
QFN52_PT04_NCP61X1S_1
  round 1.016 smd: (-4.064,-4.064) (4.064,4.064)
  oval 0.66x0.203 smd: 1(-2.913,2.4) 2(-2.913,2) 3(-2.913,1.6) 4(-2.913,1.2) 5(-2.913,0.8) 6(-2.913,0.4) 7(-2.913,0) 8(-2.913,-0.4) 9(-2.913,-0.8) 10(-2.913,-1.2) 11(-2.913,-1.6) 12(-2.913,-2) 13(-2.913,-2.4) 27(2.913,-2.4) 28(2.913,-2) 29(2.913,-1.6) 30(2.913,-1.2) 31(2.913,-0.8) 32(2.913,-0.4) 33(2.913,0) 34(2.913,0.4) 35(2.913,0.8) 36(2.913,1.2) 37(2.913,1.6) 38(2.913,2) 39(2.913,2.4)
  oval 0.203x0.66 smd: 14(-2.4,-2.913) 15(-2,-2.913) 16(-1.6,-2.913) 17(-1.2,-2.913) 18(-0.8,-2.913) 19(-0.4,-2.913) 20(0,-2.913) 21(0.4,-2.913) 22(0.8,-2.913) 23(1.2,-2.913) 24(1.6,-2.913) 25(2,-2.913) 26(2.4,-2.913) 40(2.4,2.913) 41(2,2.913) 42(1.6,2.913) 43(1.2,2.913) 44(0.8,2.913) 45(0.4,2.913) 46(0,2.913) 47(-0.4,2.913) 48(-0.8,2.913) 49(-1.2,2.913) 50(-1.6,2.913) 51(-2,2.913) 52(-2.4,2.913)
  rect 4.699x4.699 smd: 53(0,0)
R0402-SHORT_2
  custom 0.127x0.127 smd: 1(-0.508,0) 2(0.508,0)
R0402-SHORT_2-NMNP
  custom 0.127x0.127 smd: 1(-0.508,0) 2(0.508,0)
R0402_2
  oval 0.572x0.508 smd: 1(-0.476,0) 2(0.476,0)
R0603-SHORT_2
  custom 0.191x0.191 smd: 1(-0.762,0) 2(0.762,0)
R0603-SHORT_2-NMNP
  custom 0.191x0.191 smd: 1(-0.762,0) 2(0.762,0)
R0603_2
  oval 0.889x0.762 smd: 1(-0.699,0) 2(0.699,0)
R0805_2
  oval 1.016x1.397 smd: 1(-0.889,0) 2(0.889,0)
R1206
  rect 1.524x1.778 smd: 1(-1.524,0) 2(1.524,0)
R2512_1
  rect 2.032x3.302 smd: 1(-2.875,0) 2(2.875,0)
RJ3_0402
  rect 0.635x0.508 smd: 1(-1.016,0) 2(0,0) 3(1.016,0)
RJ45_USB_22P-ICOTHING_2
  round 1.27 hole 0.914: 11(7.2,12.03) 12(4.66,12.03) 13(-4.66,12.03) 14(-7.2,12.03) P1(5.715,6.66) P2(4.445,9.2) P3(3.175,6.66) P4(1.905,9.2) P5(0.635,6.66) P6(-0.635,9.2) P7(-1.905,6.66) P8(-3.175,9.2) P9(-4.445,6.66) P10(-5.715,9.2)
  round 2.692 hole 2.337: G1(6.57,-3.49) G2(-6.57,-3.49) G3(6.57,2.19) G4(-6.57,2.19) G5(9.35,-6.12) G6(-9.35,-6.12) G7(9.35,6.56) G8(-9.35,6.56)
  round 1.295 hole 0.94: U1(-3.5,-0.78) U2(-1,-0.78) U3(1,-0.78) U4(3.5,-0.78) U5(-3.5,1.84) U6(-1,1.84) U7(1,1.84) U8(3.5,1.84)
SATA3_7P-HI-TOP
  round 1.372 smd: (-1.725,-0.379) (2.085,-0.379)
  round 1.118 hole 0.762: 1(3.995,0.01) 2(2.935,1.51) 3(1.235,1.51) 4(0.18,0.01) 5(-0.875,1.51) 6(-2.565,1.51) 7(-3.63,0.01)
  round 2.134 hole 1.372: 8(6.45,0.01) 9(-6.38,1.01)
SHORT2-NMNP
  custom 0.159x0.159 smd: 1(-0.318,0) 2(0.318,0)
SOD_123_2
  rect 1.194x1.219 smd: N(1.762,0) P(-1.762,0)
SOD_523
  rect 0.6x0.8 smd: N(0.75,0) P(-0.75,0)
SOP8_W150_PT50
  rect 0.66x1.778 smd: 1(-1.905,-2.667) 2(-0.635,-2.667) 3(0.635,-2.667) 4(1.905,-2.667) 5(1.905,2.667) 6(0.635,2.667) 7(-0.635,2.667) 8(-1.905,2.667)
SOP8_W150_PT50_3D7X2D6MM
  rect 0.66x1.778 smd: 1(-1.905,-2.675) 2(-0.635,-2.675) 3(0.635,-2.675) 4(1.905,-2.675) 5(1.905,2.675) 6(0.635,2.675) 7(-0.635,2.675) 8(-1.905,2.675)
  rect 3.7x2.6 smd: 9(0,0)
SOP8_W150_PT50_3X2D5MM
  rect 0.66x1.778 smd: 1(-1.905,-2.667) 2(-0.635,-2.667) 3(0.635,-2.667) 4(1.905,-2.667) 5(1.905,2.667) 6(0.635,2.667) 7(-0.635,2.667) 8(-1.905,2.667)
  rect 3x2.5 smd: 9(0,0)
SOP8_W210_PT50_SPI_1
  rect 0.508x1.727 smd: 1(-1.905,-4) 2(-0.635,-4) 3(0.635,-4) 4(1.905,-4) 5(1.905,4) 6(0.635,4) 7(-0.635,4) 8(-1.905,4)
SOT23_2MM_2
  rect 0.864x0.864 smd: 1(-0.95,-1) 2(0.95,-1) 3(0,1)
SOT23_3L
  rect 0.914x1.422 smd: 1(-0.95,-1.05) 2(0.95,-1.05) 3(0,1.05)
SOT23_5P_1
  rect 0.686x1.346 smd: 1(-0.95,-1.24) 2(0,-1.24) 3(0.95,-1.24) 4(0.95,1.24) 5(-0.95,1.24)
SOT23_6P_2
  rect 0.508x1.27 smd: 1(-0.95,-1.25) 2(0,-1.25) 3(0.95,-1.25) 4(0.95,1.25) 5(0,1.25) 6(-0.95,1.25)
SOT23_8P_1
  rect 0.457x1.219 smd: 1(-0.975,-1.31) 2(-0.325,-1.31) 3(0.325,-1.31) 4(0.975,-1.31) 5(0.975,1.31) 6(0.325,1.31) 7(-0.325,1.31) 8(-0.975,1.31)
SOT23_BCE_2
  rect 1.016x1.016 smd: B(-1.016,-1.143) C(0,1.143) E(1.016,-1.143)
SOT23_GDS_2
  rect 1.016x1.016 smd: D(0,1.143) G(-1.016,-1.143) S(1.016,-1.143)
SOT363_6P
  rect 0.457x0.711 smd: B1(0,-1) B2(0,1) C1(-0.65,1) C2(0.65,-1) E1(-0.65,-1) E2(0.65,1)
SOT363_PT065_MOSFET
  rect 0.406x0.762 smd: 1(-0.65,-0.95) 2(0,-0.95) 3(0.65,-0.95) 4(0.65,0.95) 5(0,0.95) 6(-0.65,0.95)
TDFN14_PT04_2D5X0D9MM
  rect 0.203x0.66 smd: 1(-1.2,-0.985) 2(-0.8,-0.985) 3(-0.4,-0.985) 4(0,-0.985) 5(0.4,-0.985) 6(0.8,-0.985) 7(1.2,-0.985) 8(1.2,0.985) 9(0.8,0.985) 10(0.4,0.985) 11(0,0.985) 12(-0.4,0.985) 13(-0.8,0.985) 14(-1.2,0.985)
  rect 2.5x0.9 smd: 15(0,0)
TP30_SMD
  round 0.762 smd: 1(0,0)
TSSOP20_W170_PT065
  rect 0.305x1.778 smd: 1(-2.925,-2.9) 2(-2.275,-2.9) 3(-1.625,-2.9) 4(-0.975,-2.9) 5(-0.325,-2.9) 6(0.325,-2.9) 7(0.975,-2.9) 8(1.625,-2.9) 9(2.275,-2.9) 10(2.925,-2.9) 11(2.925,2.9) 12(2.275,2.9) 13(1.625,2.9) 14(0.975,2.9) 15(0.325,2.9) 16(-0.325,2.9) 17(-0.975,2.9) 18(-1.625,2.9) 19(-2.275,2.9) 20(-2.925,2.9)
unnamed#2
  custom 0.375x0.375 smd: (0,0)
unnamed#3
  round 3.15 hole 3.15 unplated: (-18.1,-12) (18.1,12)
USB3_18P4R-LOTES-SHORTBODY_1
  rect 1.067x1.067 hole 0.711: 1(-3.5,3.83)
  round 1.067 hole 0.711: 2(-1,3.83) 3(1,3.83) 4(3.5,3.83) 5(4,5.33) 6(2,5.33) 7(0,5.33) 8(-2,5.33) 9(-4,5.33) 10(-3.5,7.03) 11(-1,7.03) 12(1,7.03) 13(3.5,7.03) 14(4,8.53) 15(2,8.53) 16(0,8.53) 17(-2,8.53) 18(-4,8.53)
  round 2.692 hole 2.337: G1(-6.57,1.83) G2(6.57,1.83) G3(6.57,7.51) G4(-6.57,7.51)
WCM2012F2S_1
  rect 0.75x0.4 smd: 1(-0.925,0.425) 2(0.925,0.425) 3(0.925,-0.425) 4(-0.925,-0.425)

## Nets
3VR_GO: C214.2 Q21.G R242.2 R244.1
3VSBSW_L: R527.2 R536.1 U35.76
5VD_C1: C529.2 Q54.B R536.2
5VD_C2: Q54.C R540.1 R541.2 R548.2 R551.2
5VD_C3: Q53.B R540.2
5VD_C3_1: Q62.B R551.1
5VDAUL_CT3: R506.1 R507.2 R517.2
5VDAUL_CT3_1: Q52.G R517.1
5VDAUL_CT3_2: Q49.G R507.1
5VDAUL_CT3_3: Q52.D R529.2 R533.2
5VDAUL_CT3_4: C527.2 C532.1 Q57.G R533.1
5VDAUL_CT3_5: Q45.D R492.2 R506.2
5VDAUL_CT3_6: Q44.G R464.2
5VDAUL_CT7: C536.1 Q49.D Q60.G Q85.G R530.2
5VDLA: C566.1 Q62.C QN4.3 R568.2
5VDLSB: C539.1 C540.2 Q53.C Q56.G R543.2
12VR_GO: C240.2 Q24.G R274.1 R275.2
+1V05_SA: C204.1 C207.1 C209.1 C210.1 C211.2 C215.1 C219.1 CPU.AA6 CPU.AA7 CPU.AB6 CPU.AB7 CPU.AB8 CPU.AC7 CPU.AC8 CPU.N7 CPU.P7 CPU.R7 CPU.T7 CPU.U7 CPU.V7 CPU.W7 CPU.Y6 CPU.Y7 CPU.Y8 L19.2 R169.2 U18.2
+2V5_DDRVPP: C423.1 C424.1 C425.1 C444.1 C450.1 C455.1 C459.1 C460.1 C477.1 DIMM1.142 DIMM1.143 DIMM1.286 DIMM1.287 DIMM1.288 DIMM2.142 DIMM2.143 DIMM2.286 DIMM2.287 DIMM2.288 R487.2 R497.1 U29.5 U29.6
+3VSB: C201.1 C292.2 C316.1 C358.1 C371.1 C373.1 C375.1 C379.1 C381.1 C406.2 C476.1 C581.1 D19.1 D19.2 PCH1.AD41 PCH1.AJ41 PCH1.AL41 PCH1.AN5 PCH1.BA20 PCH1.BC42 PCH1.BD40 PCH1.BE41 PCH1.BE42 PCH1.BE43 PCIE16X.B10 Q13.E Q40.D R152.1 R246.2 R269.2 R305.2 R306.1 R342.1 R350.1 R351.2 R355.1 R357.1 R359.1 R378.2 R381.2 R384.2 R386.2 R388.2 R389.2 R390.2 R391.2 R392.2 R398.2 R399.1 R404.2 R405.2 R406.1 R407.2 R411.2 R412.2 R417.1 R421.1 R422.2 R423.2 R424.1 R425.2 R426.2 R427.2 R428.1 R430.2 R431.2 R457.2 R469.2 R470.2 R474.2 R492.1 R505.2 R511.2 R512.2 R521.2 R526.1 R527.1 R537.2 R541.1 R546.2 R598.2 R599.2 RJ1.1 RJ5.1 RJ6.1 RJ7.1 SP18.2 U29.3
+5V_HDMI: C3.1 C4.1 C57.1 HDMI.18 PFB1.1 R60.1 R72.1 U9.5
+5VA: C35.1 C46.1 C58.1 C61.1 CODEC.25 CODEC.38
+5VDUAL_1P0A: C537.2 C550.1 PFB5.2 Q57.D Q60.D R468.2 R617.1 R619.1
+5VSB: C118.1 C296.2 C527.1 C540.1 C544.1 C546.1 Q56.S Q57.S Q58.D R529.1 R543.1 R548.1 R554.1 R562.1 R572.1 R606.2 R622.1 RJ4.1 U14.5 U24.4 U27.2 U37.5
+12V: ATX_POWER.1 ATX_POWER.2 ATX_POWER.3 C83.1 C158.1 C170.1 C173.2 C361.1 C480.1 C515.2 C552.1 C553.1 CPU_FAN.2 D17.N D22.P EC8.1 EC21.1 FB5.1 FB6.1 FB7.1 PCIE16X.A2 PCIE16X.A3 PCIE16X.B1 PCIE16X.B2 PCIE16X.B3 PFB3.2 R91.2 R274.2 R366.2 R451.1 R485.1 R530.1 R565.1 R568.1 R608.1 R612.1 SATA_PWR.1 SATA_PWR.2
+12V_4P: ATX_12V.3 ATX_12V.4 C149.2 L15.1 SZ1.1 Z1.1
+AVCC33: L7.2 U4.1
+P1V0_PCH_VCCDSW: C359.2 PCH1.BA29
+V1P0A: C286.1 C309.1 C369.1 C374.1 C377.1 C380.1 C382.1 C383.2 C441.1 C442.1 C443.2 C449.1 C458.1 C490.2 C495.2 L28.2 PCH1.AA23 PCH1.AA26 PCH1.AA28 PCH1.AC17 PCH1.AC23 PCH1.AC26 PCH1.AC28 PCH1.AD15 PCH1.AE23 PCH1.AE26 PCH1.AJ20 PCH1.AJ21 PCH1.AJ23 PCH1.AJ25 PCH1.N17 PCH1.R17 PCH1.R19 PCH1.U20 PCH1.U21 PCH1.U23 PCH1.U25 PCH1.U26 PCH1.V17 PCH1.V26 PCH1.V28 PCH1.Y23 PCH1.Y25 R294.2 R320.2 R408.2 R416.1 R503.2 U24.1 U24.2 U24.6 U24.7 U31.2
+V1P0A_VCCAMPHYPLL: C366.2 C376.2 PCH1.A43 PCH1.B43 PCH1.C44 PCH1.C45 R408.1
+V1P0A_VCCAPLL: C291.2 C302.2 PCH1.AJ5 PCH1.AL5 PCH1.AN19 R294.1
+V1P0A_VCCF24_1P0: C323.2 C325.2 PCH1.K2 PCH1.K3 R320.1 R327.1
+V1P0A_VCCST: C143.2 C238.1 C294.1 C295.1 C308.1 CPU.V4 CPU.V5 CPU.V6 R157.2 R164.1 R165.1 R166.1 R209.1 R210.1 R259.1 R260.1 R262.1 R267.1 R295.1 R300.1 R307.1 R314.1 U24.8 U24.9 U24.13 U24.14
+VBAT: BAT1.P R318.2
+VBAT_IO: C440.1 C543.1 CLR_CMOS.2 R463.1 R550.2 U35.66
+VCC: BZ.P C117.1 C142.2 C466.2 C530.1 C531.2 C574.1 C579.2 C588.1 C591.2 D18.N D26.P EC28.1 EC29.1 L32.2 Q9.S Q85.D QN4.4 QN4.8 R85.2 R86.2 R172.1 R175.2 R187.2 R194.1 R263.2 R346.2 R494.1 R587.2 R588.1 R596.1 R610.1 R614.1 R624.1 SATA_PWR.5 SATA_PWR.6 U14.3 U27.1 U33.20 U37.3
+VCC3: C28.2 C105.1 C132.1 C162.2 C163.2 C186.1 C187.1 C188.1 C189.1 C191.1 C192.1 C193.2 C324.1 C426.1 C427.2 C445.2 C452.1 C580.2 CODEC.1 D11.2 D25.2 DIMM1.140 DIMM1.284 DIMM2.284 EC30.1 L3.1 L7.1 L20.2 PCH1.AD13 PCIE16X.A9 PCIE16X.A10 PCIE16X.B8 Q6.G Q10.G Q11.G Q12.G R27.1 R28.2 R35.1 R41.2 R101.1 R103.1 R109.1 R154.2 R155.1 R163.2 R167.2 R190.2 R217.2 R236.2 R244.2 R257.2 R301.2 R302.2 R309.2 R319.1 R353.1 R361.1 R373.2 R382.2 R396.1 R400.2 R401.2 R409.2 R410.2 R413.2 R414.2 R446.2 R456.2 R458.1 R480.2 R491.2 R499.1 R515.2 R544.2 R555.2 R560.2 R561.2 R591.1 R601.1 RJ1.3 RJ2.1 TCM.9 U4.14 U4.26
+VCCGT: C253.1 C257.1 C261.1 C268.1 C272.1 C281.1 C285.1 C290.1 C301.1 C315.1 C321.1 CPU.AA34 CPU.AA35 CPU.AA36 CPU.AA37 CPU.AA38 CPU.AB33 CPU.AB34 CPU.G36 CPU.G37 CPU.G38 CPU.G39 CPU.G40 CPU.H36 CPU.H38 CPU.H40 CPU.J36 CPU.J37 CPU.J38 CPU.J39 CPU.J40 CPU.K36 CPU.K38 CPU.K40 CPU.L34 CPU.L35 CPU.L36 CPU.L37 CPU.L38 CPU.L39 CPU.L40 CPU.M33 CPU.M34 CPU.M36 CPU.M38 CPU.M40 CPU.N34 CPU.N35 CPU.N36 CPU.N37 CPU.N38 CPU.N39 CPU.N40 CPU.P33 CPU.P34 CPU.P36 CPU.P38 CPU.P40 CPU.R34 CPU.R35 CPU.R36 CPU.R37 CPU.R38 CPU.R39 CPU.R40 CPU.T33 CPU.T34 CPU.T36 CPU.T38 CPU.T40 CPU.U34 CPU.U35 CPU.U36 CPU.U37 CPU.U38 CPU.U39 CPU.U40 CPU.V33 CPU.V34 CPU.V36 CPU.V38 CPU.V40 CPU.W34 CPU.W35 CPU.W36 CPU.W37 CPU.W38 CPU.Y33 CPU.Y34 CPU.Y36 CPU.Y38 EC16.1 EC17.1 EC18.1 EC20.1 L23.2 L24.2 R160.2 SC2.1 SP11.1 SP13.1
+VCCGT_PH1: C260.1 L23.1 QCGH1.S1 QCGH1.S2 QCGH1.S3 QCGL1.D1 QCGL1.D2 QCGL1.D3 QCGL1.D4 QCGL1.D5 QCGL3.D1 QCGL3.D2 QCGL3.D3 QCGL3.D4 QCGL3.D5 R273.2 R278.1 SP12.1 U23.7
+VCCGT_PH1_R: C236.2 R273.1
+VCCGT_PH2: C337.1 L24.1 QCGH2.S1 QCGH2.S2 QCGH2.S3 QCGL2.D1 QCGL2.D2 QCGL2.D3 QCGL2.D4 QCGL2.D5 QCGL4.D1 QCGL4.D2 QCGL4.D3 QCGL4.D4 QCGL4.D5 R328.1 R331.2 SP14.1 U25.7
+VCCGT_PH2_R: C334.2 R331.1
+VCCHDA: PCH1.BA15 SP18.1
+VCCIO: C264.1 C267.1 C273.1 C274.1 C276.2 C277.1 C284.1 C293.1 C297.1 C311.1 C317.1 CPU.AJ23 CPU.AK11 CPU.AK14 CPU.AK24 CPU.M8 CPU.P8 CPU.T8 CPU.U8 CPU.W8 L22.2 R234.2 R249.2 R289.2 R290.1 U22.2
+VCCK_V12: C11.2 C16.2 C49.2 U4.4 U4.25
+VCCPFUSE_3P3: PCH1.BD3 PCH1.BE3 PCH1.BE4 R306.2
+VCCPGPPA: PCH1.BA31 R417.2
+VCCPGPPD: PCH1.BA45 PCH1.BB45 PCH1.BC44 PCH1.BC45 R399.2
+VCCPLL_OC_R: CPU.AJ9 R321.1
+VCCPRIM_1P0: PCH1.AL22 R416.2
+VDD1.0: C146.1 C147.1 C148.1 C165.1 C181.1 C185.1 R213.2 U19.3 U19.8 U19.22 U19.30
+VDD33: C94.2 C96.2 C97.1 C152.2 C155.2 C159.2 C195.2 D8.N FB4.2 Q15.D R121.2 R130.2 R131.2 R170.1 R193.2 U11.5 U12.5 U19.11 U19.32 USB2_LAN.14
+VDD_DAC_33: C5.2 L3.2 U4.20
+VIN_CPU: C120.2 C133.2 C134.2 C135.2 C137.2 C151.2 C196.2 C208.2 C217.2 C241.2 C246.2 C255.2 C322.2 C326.2 EC7.1 EC9.1 EC19.1 L15.2 PFB2.2 PFB4.2 QCGH1.D1 QCGH1.D2 QCGH1.D3 QCGH1.D4 QCGH1.D5 QCGH2.D1 QCGH2.D2 QCGH2.D3 QCGH2.D4 QCGH2.D5 QCH1.D1 QCH1.D2 QCH1.D3 QCH1.D4 QCH1.D5 QCH2.D1 QCH2.D2 QCH2.D3 QCH2.D4 QCH2.D5 QCH3.D1 QCH3.D2 QCH3.D3 QCH3.D4 QCH3.D5 R162.2 R338.2 SZ1.2 Z1.2
-12V: ATX_POWER.4 C494.1 C555.1 C556.1 D23.N
AVDDREG1: FB4.1 U19.23
